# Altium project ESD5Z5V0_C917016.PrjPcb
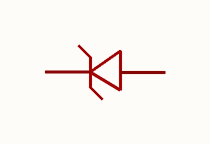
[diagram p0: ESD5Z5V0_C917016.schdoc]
1 sheet, 1 parts. Net scope: global (net labels, ports and power ports of the same name join across sheets).

## Sheet ESD5Z5V0_C917016.schdoc
size 127 x 101 mm

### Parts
D?  esd5z5v0_c917016  [SOD-523_L1.2-W0.8-LS1.6-RD]  (value not drawn)

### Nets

Not connected (* = marked no-connect by the designer): D? 1(C) 2(A)

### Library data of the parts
D? = esd5z5v0_c917016: 极性:单向;反向截止电压(Vrwm):5V;钳位电压:15V;峰值脉冲电流(Ipp):-;峰值脉冲功率(Ppp):150mW;击穿电压(VBR):6.2V;; Manufacturer: JSMSEMI(杰盛微); AddInBom: yes; ModelId: 8f56a03db567494d8f4c9d12aa52a741; ModelName: SOD-523_L1.2-W0.8-H0.7-LS1.6; ModelTransform: 62.992,31.496,0,180,0,0,0,0,0; Polarity: 单向; Reverse Stand-Off Voltage (Vrwm): 5V; Clamping Voltage: 15V; Peak Pulse Power Dissipation (Ppp): 150mW; Voltage - Breakdown: 6.2V; Reverse Leakage Current (Ir): 80nA; Number of Channels: 单路; level of protection: IEC 61000-4-2; Type: ESD; Junction Capacitance: 80pF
